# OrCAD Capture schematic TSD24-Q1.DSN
size A; title: TSDxx-Q1 Unidirectional Protection Diodes in SOD-323; rev: 1.0; note: Datasheet: SLVSHX1
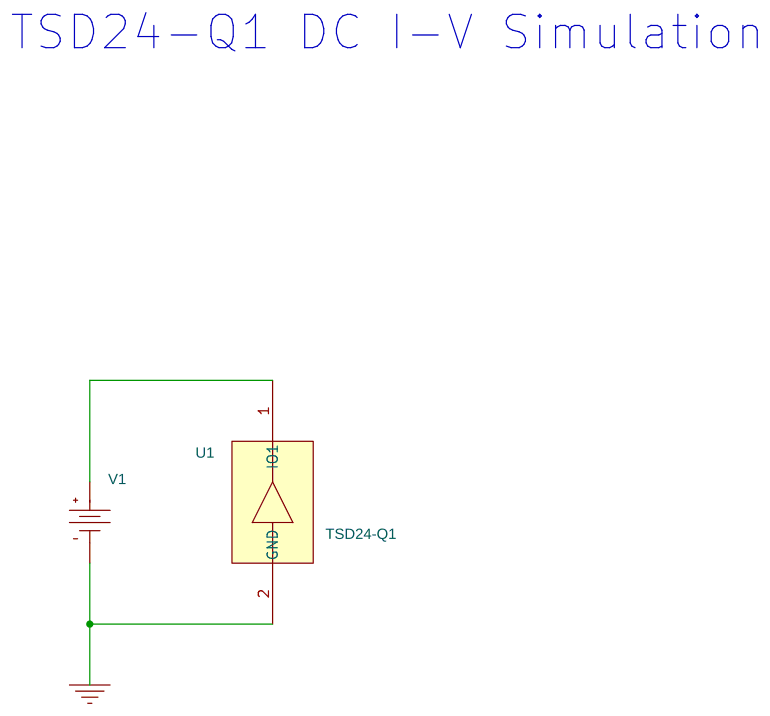
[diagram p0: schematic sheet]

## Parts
U1  TSD24-Q1
V1  VDC

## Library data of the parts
U1 = TSD24-Q1
V1 = VDC

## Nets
0: U1.2(GND) V1.1(-)
N02957: U1.1(IO1) V1.0(+)

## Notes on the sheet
- TSD24-Q1 DC I-V Simulation
